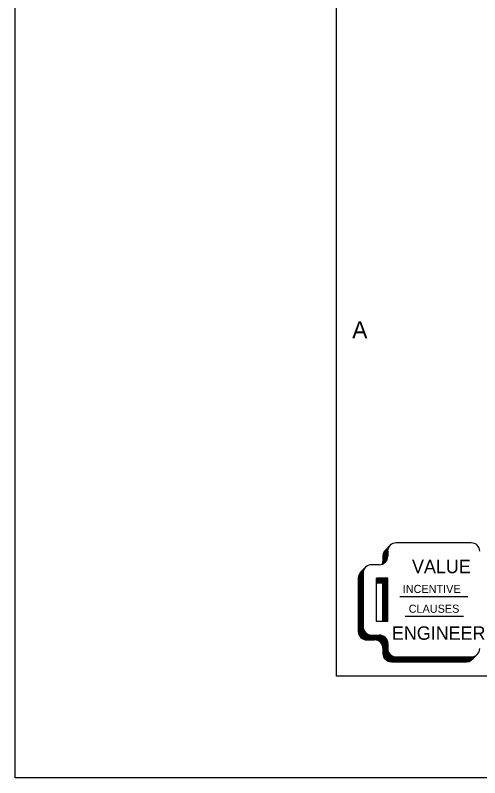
# Model space of a CAD drawing. Extents: x 22371.58 to 22374.41, y 22370.57 to 22372.4.
# Drawn here: x 22371.5783 to 22371.8644, y 22370.5694 to 22371.0393 of the extents above; entities that cross this region are included whole.
import ezdxf

# ---------------------------------------------------------------- set-up
doc = ezdxf.new("R2010")
doc.units = 0
for name, color, linetype in [('G-ANNO-SYMB', 7, 'Continuous'), ('G-ANNO-TEXT', 7, 'Continuous'), ('G-ANNO-TTBL', 7, 'Continuous'), ('S-SECT-GENF', 7, 'Continuous')]:
    doc.layers.add(name, color=color, linetype=linetype)

msp = doc.modelspace()

# ---------------------------------------------------------------- linework, layer by layer
at = {"layer": 'G-ANNO-SYMB'}
msp.add_lwpolyline([(22371.57831, 22372.40278), (22374.41164, 22372.40278), (22374.41164, 22370.56945), (22371.57831, 22370.56945)], close=True, dxfattribs=at)
at = {"layer": 'G-ANNO-TTBL'}
msp.add_lwpolyline([(22371.77622, 22372.34028), (22374.19289, 22372.34028), (22374.19289, 22370.63195), (22371.77622, 22370.63195)], close=True, dxfattribs=at)
msp.add_lwpolyline([(22371.77622, 22372.34028), (22374.19289, 22372.34028), (22374.19289, 22370.63195), (22371.77622, 22370.63195)], close=True, dxfattribs=at)
at = {"layer": 'S-SECT-GENF'}
for p, q in [((22371.80623, 22370.70973), (22371.80918, 22370.71268)), ((22371.80844, 22370.71173), (22371.80844, 22370.71194)), ((22371.80866, 22370.71206), (22371.80866, 22370.71216)), ((22371.85916, 22370.7142), (22371.81287, 22370.7142)), ((22371.80499, 22370.70773), (22371.80499, 22370.70137)), ((22371.80535, 22370.70853), (22371.80535, 22370.70158)), ((22371.80567, 22370.70905), (22371.80567, 22370.70182)), ((22371.80602, 22370.7095), (22371.80602, 22370.70212)), ((22371.80637, 22370.70986), (22371.80637, 22370.70248)), ((22371.80672, 22370.71022), (22371.80672, 22370.70294)), ((22371.8071, 22370.71059), (22371.8071, 22370.70356)), ((22371.80745, 22370.71095), (22371.80745, 22370.70446)), ((22371.80766, 22370.70899), (22371.80766, 22370.71116)), ((22371.80766, 22370.70899), (22371.80766, 22370.70592)), ((22371.80791, 22370.71058), (22371.80791, 22370.71141)), ((22371.80818, 22370.71126), (22371.80818, 22370.71168)), ((22371.80471, 22370.70604), (22371.80471, 22370.70123)), ((22371.79111, 22370.69624), (22371.79405, 22370.69919)), ((22371.79265, 22370.69658), (22371.79265, 22370.69778)), ((22371.79279, 22370.69712), (22371.79279, 22370.69793)), ((22371.79291, 22370.69744), (22371.79291, 22370.69804)), ((22371.79301, 22370.69768), (22371.79301, 22370.69814)), ((22371.79311, 22370.69787), (22371.79311, 22370.69824)), ((22371.79321, 22370.69807), (22371.79321, 22370.69834)), ((22371.79331, 22370.69824), (22371.79331, 22370.69845)), ((22371.79342, 22370.69841), (22371.79342, 22370.69855)), ((22371.79352, 22370.69855), (22371.79352, 22370.69866)), ((22371.80245, 22370.70071), (22371.79774, 22370.70071)), ((22371.78973, 22370.69377), (22371.78973, 22370.65842)), ((22371.78989, 22370.6943), (22371.78989, 22370.65788)), ((22371.79005, 22370.69471), (22371.79005, 22370.65748)), ((22371.79019, 22370.69499), (22371.79019, 22370.6572)), ((22371.79036, 22370.69528), (22371.79036, 22370.65691)), ((22371.79052, 22370.69553), (22371.79052, 22370.65666)), ((22371.7907, 22370.69577), (22371.7907, 22370.65642)), ((22371.79085, 22370.69595), (22371.79085, 22370.65624)), ((22371.79098, 22370.6961), (22371.79098, 22370.65608)), ((22371.79113, 22370.69625), (22371.79113, 22370.65594)), ((22371.7913, 22370.69644), (22371.7913, 22370.65577)), ((22371.79143, 22370.69656), (22371.79143, 22370.65566)), ((22371.79156, 22370.6967), (22371.79156, 22370.65555)), ((22371.79173, 22370.69686), (22371.79173, 22370.65543)), ((22371.79191, 22370.69704), (22371.79191, 22370.6553)), ((22371.79205, 22370.69719), (22371.79205, 22370.65521)), ((22371.79219, 22370.69732), (22371.79219, 22370.65512)), ((22371.79233, 22370.69746), (22371.79233, 22370.65505)), ((22371.79242, 22370.69755), (22371.79242, 22370.655)), ((22371.79253, 22370.6955), (22371.79253, 22370.69767)), ((22371.79253, 22370.6955), (22371.79253, 22370.66258)), ((22371.78959, 22370.69255), (22371.78959, 22370.65963)), ((22371.80766, 22370.69237), (22371.80076, 22370.69237)), ((22371.80076, 22370.66571), (22371.80076, 22370.69237)), ((22371.80766, 22370.69224), (22371.80076, 22370.69224)), ((22371.80766, 22370.6921), (22371.80076, 22370.6921)), ((22371.80766, 22370.69195), (22371.80076, 22370.69195)), ((22371.80766, 22370.69179), (22371.80076, 22370.69179)), ((22371.80766, 22370.69162), (22371.80076, 22370.69162)), ((22371.80766, 22370.69147), (22371.80076, 22370.69147)), ((22371.80766, 22370.69131), (22371.80076, 22370.69131)), ((22371.80766, 22370.69114), (22371.80076, 22370.69114)), ((22371.80766, 22370.691), (22371.80076, 22370.691)), ((22371.80766, 22370.69084), (22371.80076, 22370.69084)), ((22371.80766, 22370.69069), (22371.80076, 22370.69069)), ((22371.80766, 22370.69054), (22371.80076, 22370.69054)), ((22371.80766, 22370.69039), (22371.80076, 22370.69039)), ((22371.80766, 22370.69027), (22371.80076, 22370.69027)), ((22371.80766, 22370.69011), (22371.80076, 22370.69011)), ((22371.80766, 22370.68999), (22371.80076, 22370.68999)), ((22371.80766, 22370.68985), (22371.80076, 22370.68985)), ((22371.80766, 22370.68973), (22371.80076, 22370.68973)), ((22371.80766, 22370.68957), (22371.80076, 22370.68957)), ((22371.80471, 22370.68943), (22371.80076, 22370.68943)), ((22371.80766, 22370.69237), (22371.80471, 22370.68943)), ((22371.80471, 22370.66571), (22371.80471, 22370.68943)), ((22371.80486, 22370.66571), (22371.80486, 22370.68957)), ((22371.80497, 22370.66571), (22371.80497, 22370.68957)), ((22371.8051, 22370.66571), (22371.8051, 22370.68957)), ((22371.8052, 22370.66571), (22371.8052, 22370.68957)), ((22371.80536, 22370.66571), (22371.80536, 22370.68957)), ((22371.80549, 22370.66571), (22371.80549, 22370.68957)), ((22371.80564, 22370.66571), (22371.80564, 22370.68957)), ((22371.80574, 22370.66571), (22371.80574, 22370.68957)), ((22371.80591, 22370.66571), (22371.80591, 22370.68957)), ((22371.80604, 22370.66571), (22371.80604, 22370.68957)), ((22371.80616, 22370.66571), (22371.80616, 22370.68957)), ((22371.80629, 22370.66571), (22371.80629, 22370.68957)), ((22371.80643, 22370.66571), (22371.80643, 22370.68957)), ((22371.80659, 22370.66571), (22371.80659, 22370.68957)), ((22371.80671, 22370.66571), (22371.80671, 22370.68957)), ((22371.80684, 22370.66571), (22371.80684, 22370.68957)), ((22371.80699, 22370.66571), (22371.80699, 22370.68957)), ((22371.80715, 22370.66571), (22371.80715, 22370.68957)), ((22371.8073, 22370.66571), (22371.8073, 22370.68957)), ((22371.80741, 22370.66571), (22371.80741, 22370.68957)), ((22371.80754, 22370.66571), (22371.80754, 22370.68957)), ((22371.80766, 22370.66571), (22371.80766, 22370.69237)), ((22371.81521, 22370.68105), (22371.85703, 22370.68105)), ((22371.80766, 22370.66571), (22371.80076, 22370.66571)), ((22371.81836, 22370.66905), (22371.85445, 22370.66905)), ((22371.79261, 22370.66172), (22371.79261, 22370.65491)), ((22371.79277, 22370.66102), (22371.79277, 22370.65483)), ((22371.79293, 22370.66059), (22371.79293, 22370.65477)), ((22371.79309, 22370.66025), (22371.79309, 22370.65472)), ((22371.79327, 22370.65991), (22371.79327, 22370.65466)), ((22371.79341, 22370.6597), (22371.79341, 22370.65461)), ((22371.79354, 22370.6595), (22371.79354, 22370.65458)), ((22371.79372, 22370.65927), (22371.79372, 22370.65454)), ((22371.79387, 22370.6591), (22371.79387, 22370.65451)), ((22371.79402, 22370.65894), (22371.79402, 22370.65449)), ((22371.79418, 22370.65878), (22371.79418, 22370.65446)), ((22371.79434, 22370.65864), (22371.79434, 22370.65445)), ((22371.79448, 22370.65852), (22371.79448, 22370.65444)), ((22371.79466, 22370.65838), (22371.79466, 22370.65443)), ((22371.79481, 22370.65827), (22371.79481, 22370.65443)), ((22371.79497, 22370.65818), (22371.79497, 22370.65443)), ((22371.79513, 22370.65808), (22371.79513, 22370.65443)), ((22371.79531, 22370.65798), (22371.79531, 22370.65443)), ((22371.79545, 22370.65791), (22371.79545, 22370.65443)), ((22371.79553, 22370.65786), (22371.79553, 22370.65443)), ((22371.79567, 22370.6578), (22371.79567, 22370.65443)), ((22371.7958, 22370.65775), (22371.7958, 22370.65443)), ((22371.79597, 22370.65769), (22371.79597, 22370.65443)), ((22371.79614, 22370.65762), (22371.79614, 22370.65443)), ((22371.79629, 22370.65758), (22371.79629, 22370.65443)), ((22371.7965, 22370.65752), (22371.7965, 22370.65443)), ((22371.79669, 22370.65748), (22371.79669, 22370.65443)), ((22371.79685, 22370.65745), (22371.79685, 22370.65443)), ((22371.79696, 22370.65744), (22371.79696, 22370.65443)), ((22371.79712, 22370.65742), (22371.79712, 22370.65443)), ((22371.79725, 22370.65739), (22371.79725, 22370.65443)), ((22371.79737, 22370.65738), (22371.79737, 22370.65443)), ((22371.79751, 22370.65737), (22371.79751, 22370.65443)), ((22371.79768, 22370.65737), (22371.79768, 22370.65443)), ((22371.79774, 22370.65737), (22371.80245, 22370.65737)), ((22371.79784, 22370.65737), (22371.79784, 22370.65443)), ((22371.79801, 22370.65737), (22371.79801, 22370.65443)), ((22371.79819, 22370.65737), (22371.79819, 22370.65443)), ((22371.79835, 22370.65737), (22371.79835, 22370.65443)), ((22371.79855, 22370.65737), (22371.79855, 22370.65443)), ((22371.79873, 22370.65737), (22371.79873, 22370.65443)), ((22371.79889, 22370.65737), (22371.79889, 22370.65443)), ((22371.79906, 22370.65737), (22371.79906, 22370.65443)), ((22371.79926, 22370.65737), (22371.79926, 22370.65443)), ((22371.79945, 22370.65737), (22371.79945, 22370.65443)), ((22371.79965, 22370.65737), (22371.79965, 22370.65443)), ((22371.79985, 22370.65737), (22371.79985, 22370.65443)), ((22371.80008, 22370.65737), (22371.80008, 22370.65439)), ((22371.80023, 22370.65737), (22371.80023, 22370.65437)), ((22371.80037, 22370.65737), (22371.80037, 22370.65435)), ((22371.8005, 22370.65737), (22371.8005, 22370.65433)), ((22371.80072, 22370.65737), (22371.80072, 22370.65428)), ((22371.80095, 22370.65737), (22371.80095, 22370.65422)), ((22371.80119, 22370.65737), (22371.80119, 22370.65414)), ((22371.80142, 22370.65737), (22371.80142, 22370.65406)), ((22371.80162, 22370.65737), (22371.80162, 22370.65398)), ((22371.80185, 22370.65737), (22371.80185, 22370.65387)), ((22371.80202, 22370.65737), (22371.80202, 22370.65378)), ((22371.80229, 22370.65737), (22371.80229, 22370.65361)), ((22371.80251, 22370.65737), (22371.80251, 22370.65347)), ((22371.80263, 22370.65737), (22371.80263, 22370.65338)), ((22371.80283, 22370.65737), (22371.80283, 22370.65323)), ((22371.80298, 22370.65734), (22371.80298, 22370.65309)), ((22371.80315, 22370.65732), (22371.80315, 22370.65294)), ((22371.8033, 22370.6573), (22371.8033, 22370.65278)), ((22371.80342, 22370.65728), (22371.80342, 22370.65266)), ((22371.8036, 22370.65725), (22371.8036, 22370.65244)), ((22371.80377, 22370.65721), (22371.80377, 22370.6522)), ((22371.80396, 22370.65716), (22371.80396, 22370.65191)), ((22371.80414, 22370.65709), (22371.80414, 22370.65159)), ((22371.80429, 22370.65704), (22371.80429, 22370.65126)), ((22371.80446, 22370.65697), (22371.80446, 22370.65081)), ((22371.80464, 22370.65689), (22371.80464, 22370.65008)), ((22371.80477, 22370.65683), (22371.80477, 22370.64534)), ((22371.80494, 22370.65674), (22371.80494, 22370.64461)), ((22371.80511, 22370.65664), (22371.80511, 22370.64416)), ((22371.80526, 22370.65655), (22371.80526, 22370.64381)), ((22371.80542, 22370.65645), (22371.80542, 22370.64352)), ((22371.80558, 22370.65633), (22371.80558, 22370.64327)), ((22371.80575, 22370.6562), (22371.80575, 22370.64302)), ((22371.80589, 22370.65608), (22371.80589, 22370.64284)), ((22371.80604, 22370.65594), (22371.80604, 22370.64267)), ((22371.80618, 22370.6558), (22371.80618, 22370.64252)), ((22371.80635, 22370.65562), (22371.80635, 22370.64235)), ((22371.79479, 22370.65443), (22371.7995, 22370.65443)), ((22371.8065, 22370.65544), (22371.8065, 22370.64222)), ((22371.80668, 22370.65521), (22371.80668, 22370.64206)), ((22371.80685, 22370.65496), (22371.80685, 22370.64194)), ((22371.80698, 22370.65474), (22371.80698, 22370.64184)), ((22371.80711, 22370.6545), (22371.80711, 22370.64176)), ((22371.80721, 22370.65428), (22371.80721, 22370.6417)), ((22371.80735, 22370.65395), (22371.80735, 22370.64161)), ((22371.80746, 22370.65359), (22371.80746, 22370.64155)), ((22371.80755, 22370.6532), (22371.80755, 22370.6415)), ((22371.80766, 22370.65217), (22371.80766, 22370.64909)), ((22371.80471, 22370.64922), (22371.80471, 22370.64614)), ((22371.80767, 22370.64876), (22371.80767, 22370.64145)), ((22371.80781, 22370.64782), (22371.80781, 22370.64138)), ((22371.80795, 22370.64737), (22371.80795, 22370.64132)), ((22371.80806, 22370.64707), (22371.80806, 22370.64128)), ((22371.80819, 22370.6468), (22371.80819, 22370.64123)), ((22371.80829, 22370.6466), (22371.80829, 22370.6412)), ((22371.80844, 22370.64635), (22371.80844, 22370.64116)), ((22371.80858, 22370.64614), (22371.80858, 22370.64111)), ((22371.80872, 22370.64594), (22371.80872, 22370.64107)), ((22371.80883, 22370.64581), (22371.80883, 22370.64105)), ((22371.80897, 22370.64563), (22371.80897, 22370.64102)), ((22371.80905, 22370.64554), (22371.80905, 22370.64101)), ((22371.80917, 22370.64543), (22371.80917, 22370.64099)), ((22371.80929, 22370.6453), (22371.80929, 22370.64098)), ((22371.80939, 22370.64522), (22371.80939, 22370.64097)), ((22371.80945, 22370.64517), (22371.80945, 22370.64096)), ((22371.80952, 22370.6451), (22371.80952, 22370.64095)), ((22371.80964, 22370.64501), (22371.80964, 22370.64095)), ((22371.80978, 22370.64489), (22371.80978, 22370.64095)), ((22371.80995, 22370.64478), (22371.80995, 22370.64095)), ((22371.8101, 22370.64469), (22371.8101, 22370.64095)), ((22371.81026, 22370.64458), (22371.81026, 22370.64095)), ((22371.81042, 22370.6445), (22371.81042, 22370.64095)), ((22371.81058, 22370.64442), (22371.81058, 22370.64095)), ((22371.8107, 22370.64435), (22371.8107, 22370.64095)), ((22371.81085, 22370.64429), (22371.81085, 22370.64095)), ((22371.81101, 22370.64423), (22371.81101, 22370.64095)), ((22371.81118, 22370.64417), (22371.81118, 22370.64095)), ((22371.81135, 22370.64411), (22371.81135, 22370.64095)), ((22371.81152, 22370.64406), (22371.81152, 22370.64095)), ((22371.81171, 22370.64401), (22371.81171, 22370.64095)), ((22371.81186, 22370.64398), (22371.81186, 22370.64095)), ((22371.81204, 22370.64395), (22371.81204, 22370.64095)), ((22371.81221, 22370.64393), (22371.81221, 22370.64095)), ((22371.81238, 22370.64391), (22371.81238, 22370.64095)), ((22371.81258, 22370.64389), (22371.81258, 22370.64095)), ((22371.81274, 22370.64388), (22371.81274, 22370.64095)), ((22371.81274, 22370.64381), (22371.85621, 22370.64381)), ((22371.81274, 22370.64376), (22371.85621, 22370.64376)), ((22371.81274, 22370.64371), (22371.85621, 22370.64371)), ((22371.81274, 22370.64363), (22371.85621, 22370.64363)), ((22371.81274, 22370.64355), (22371.85621, 22370.64355)), ((22371.81274, 22370.64346), (22371.85621, 22370.64346)), ((22371.81274, 22370.64336), (22371.85621, 22370.64336)), ((22371.81274, 22370.64328), (22371.85621, 22370.64328)), ((22371.81274, 22370.64319), (22371.85621, 22370.64319)), ((22371.81274, 22370.64309), (22371.85621, 22370.64309)), ((22371.81274, 22370.643), (22371.85621, 22370.643)), ((22371.81274, 22370.64291), (22371.85621, 22370.64291)), ((22371.81274, 22370.64281), (22371.85621, 22370.64281)), ((22371.81274, 22370.64273), (22371.85621, 22370.64273)), ((22371.81274, 22370.64263), (22371.85621, 22370.64263)), ((22371.81274, 22370.64255), (22371.85621, 22370.64255)), ((22371.81274, 22370.64247), (22371.85621, 22370.64247)), ((22371.81274, 22370.64237), (22371.85621, 22370.64237)), ((22371.81274, 22370.64228), (22371.85621, 22370.64228)), ((22371.81274, 22370.64218), (22371.85621, 22370.64218)), ((22371.81274, 22370.64207), (22371.85621, 22370.64207)), ((22371.81274, 22370.64197), (22371.85621, 22370.64197)), ((22371.81274, 22370.64187), (22371.85621, 22370.64187)), ((22371.81274, 22370.64176), (22371.85621, 22370.64176)), ((22371.81274, 22370.64166), (22371.85621, 22370.64166)), ((22371.81274, 22370.64154), (22371.85621, 22370.64154)), ((22371.81274, 22370.64143), (22371.85621, 22370.64143)), ((22371.81287, 22370.64388), (22371.85916, 22370.64388)), ((22371.85621, 22370.64094), (22371.85621, 22370.64388)), ((22371.85633, 22370.64094), (22371.85633, 22370.64388)), ((22371.85641, 22370.64094), (22371.85641, 22370.64388)), ((22371.85649, 22370.64095), (22371.85649, 22370.64388)), ((22371.85663, 22370.64096), (22371.85663, 22370.64388)), ((22371.85673, 22370.64097), (22371.85673, 22370.64388)), ((22371.85686, 22370.64098), (22371.85686, 22370.64388)), ((22371.85696, 22370.64099), (22371.85696, 22370.64388)), ((22371.85708, 22370.64101), (22371.85708, 22370.64388)), ((22371.85717, 22370.64103), (22371.85717, 22370.64388)), ((22371.85729, 22370.64105), (22371.85729, 22370.64388)), ((22371.85741, 22370.64107), (22371.85741, 22370.64388)), ((22371.85752, 22370.6411), (22371.85752, 22370.64388)), ((22371.85767, 22370.64114), (22371.85767, 22370.64388)), ((22371.85783, 22370.6412), (22371.85783, 22370.64388)), ((22371.85795, 22370.64124), (22371.85795, 22370.64388)), ((22371.85808, 22370.64128), (22371.85808, 22370.64388)), ((22371.85821, 22370.64133), (22371.85821, 22370.64388)), ((22371.85835, 22370.64139), (22371.85835, 22370.64388)), ((22371.85846, 22370.64145), (22371.85846, 22370.64388)), ((22371.85862, 22370.64153), (22371.85862, 22370.64388)), ((22371.85877, 22370.64161), (22371.85877, 22370.64388)), ((22371.85892, 22370.6417), (22371.85892, 22370.64388)), ((22371.85906, 22370.64179), (22371.85906, 22370.64388)), ((22371.85921, 22370.64188), (22371.85921, 22370.64388)), ((22371.85935, 22370.64199), (22371.85935, 22370.64388)), ((22371.85949, 22370.6421), (22371.85949, 22370.64388)), ((22371.85965, 22370.64223), (22371.85965, 22370.64391)), ((22371.85979, 22370.64236), (22371.85979, 22370.64393)), ((22371.8599, 22370.64246), (22371.86285, 22370.64541)), ((22371.85992, 22370.64248), (22371.85992, 22370.64394)), ((22371.86005, 22370.64261), (22371.86005, 22370.64396)), ((22371.86016, 22370.64272), (22371.86016, 22370.64398)), ((22371.86028, 22370.64284), (22371.86028, 22370.64401)), ((22371.86039, 22370.64295), (22371.86039, 22370.64403)), ((22371.8605, 22370.64306), (22371.8605, 22370.64406)), ((22371.86063, 22370.64319), (22371.86063, 22370.64409)), ((22371.86071, 22370.64327), (22371.86071, 22370.64412)), ((22371.86081, 22370.64337), (22371.86081, 22370.64416)), ((22371.86091, 22370.64347), (22371.86091, 22370.64419)), ((22371.86101, 22370.64357), (22371.86101, 22370.64423)), ((22371.86108, 22370.64363), (22371.86108, 22370.64425)), ((22371.8612, 22370.64376), (22371.8612, 22370.6443)), ((22371.86129, 22370.64385), (22371.86129, 22370.64434)), ((22371.8614, 22370.64396), (22371.8614, 22370.64439)), ((22371.86151, 22370.64407), (22371.86151, 22370.64445)), ((22371.86161, 22370.64417), (22371.86161, 22370.6445)), ((22371.8617, 22370.64426), (22371.8617, 22370.64455)), ((22371.86179, 22370.64435), (22371.86179, 22370.6446)), ((22371.8619, 22370.64446), (22371.8619, 22370.64467)), ((22371.862, 22370.64456), (22371.862, 22370.64473)), ((22371.8621, 22370.64466), (22371.8621, 22370.64479)), ((22371.86219, 22370.64475), (22371.86219, 22370.64485)), ((22371.86228, 22370.64484), (22371.86228, 22370.64493)), ((22371.80992, 22370.64094), (22371.85621, 22370.64094)), ((22371.81274, 22370.6413), (22371.85621, 22370.6413)), ((22371.81274, 22370.64119), (22371.85621, 22370.64119)), ((22371.81274, 22370.64107), (22371.85621, 22370.64107))]:
    msp.add_line(p, q, dxfattribs=at)
for centre, start, end in [((22371.81286, 22370.70898), 90, 180), ((22371.85916, 22370.70898), 0, 90), ((22371.80992, 22370.70604), 111.4079, 180), ((22371.80245, 22370.70591), 270, 0), ((22371.7995, 22370.70296), 338.5921, 0), ((22371.79774, 22370.69549), 90, 180), ((22371.79479, 22370.69255), 111.4079, 180), ((22371.79774, 22370.66258), 180, 270), ((22371.79479, 22370.65963), 180, 270), ((22371.80245, 22370.65216), 0, 90), ((22371.7995, 22370.64921), 0, 90), ((22371.80992, 22370.64614), 180, 270), ((22371.81286, 22370.64909), 180, 270), ((22371.85916, 22370.64909), 270, 0), ((22371.85621, 22370.64614), 270, 338.5921)]:
    msp.add_arc(centre, 0.00521, start, end, dxfattribs=at)

# ---------------------------------------------------------------- texts
at = {"layer": 'G-ANNO-TEXT'}
msp.add_text('A', height=0.01042, dxfattribs=at).set_placement((22371.78585, 22370.84028))
at = {"layer": 'S-SECT-GENF'}
for s, height, p in [('VALUE', 0.008249, (22371.82265, 22370.6955)), ('INCENTIVE', 0.005, (22371.81694, 22370.68329)), ('CLAUSES', 0.005, (22371.82061, 22370.6711)), ('ENGINEERING', 0.0082494, (22371.81029, 22370.65447))]:
    msp.add_text(s, height=height, dxfattribs=at).set_placement(p)

doc.saveas('drawing.dxf')
